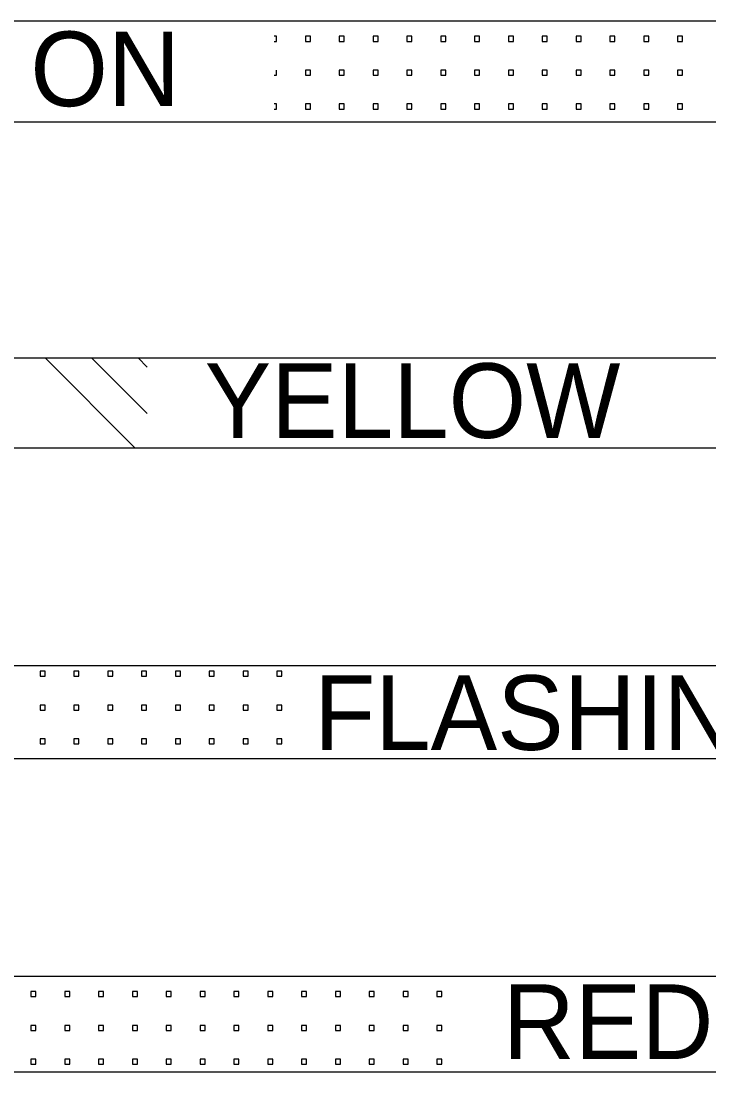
# Model space of a CAD drawing. Extents: x 15 to 764, y 7 to 487.
# Drawn here: x 610.69 to 642.97, y 134.67 to 183.98 of the extents above; entities that cross this region are included whole.
import ezdxf

# ---------------------------------------------------------------- set-up
doc = ezdxf.new("R2010")
doc.units = 0
doc.layers.add('Default', color=7, linetype='Continuous')
doc.layers.add('TextStructures', color=7, linetype='Continuous')

msp = doc.modelspace()

# ---------------------------------------------------------------- linework, layer by layer
at = {"layer": 'Default'}
for p, q in [((756.61, 183.984), (462.687, 183.984)), ((462.687, 179.246), (756.61, 179.246)), ((462.687, 168.178), (756.61, 168.178)), ((462.687, 163.965), (756.61, 163.965)), ((462.687, 153.744), (756.61, 153.744)), ((462.687, 149.383), (756.61, 149.383)), ((462.687, 139.163), (756.61, 139.163)), ((462.687, 134.675), (756.61, 134.675))]:
    msp.add_line(p, q, dxfattribs=at)
for points in [[(622.677, 183.27), (622.573, 183.269)], [(622.573, 183.03), (622.677, 183.03)], [(622.677, 183.03), (622.677, 183.27)], [(624.267, 183.03), (624.267, 183.27), (624.03, 183.269), (624.03, 183.03), (624.267, 183.03)], [(624.267, 183.03), (624.267, 183.27), (624.03, 183.269), (624.03, 183.03), (624.267, 183.03)], [(625.853, 183.03), (625.853, 183.27), (625.617, 183.269), (625.617, 183.03), (625.853, 183.03)], [(625.853, 183.03), (625.853, 183.27), (625.617, 183.269), (625.617, 183.03), (625.853, 183.03)], [(627.443, 183.03), (627.443, 183.27), (627.207, 183.269), (627.207, 183.03), (627.443, 183.03)], [(627.443, 183.03), (627.443, 183.27), (627.207, 183.269), (627.207, 183.03), (627.443, 183.03)], [(629.03, 183.03), (629.03, 183.27), (628.793, 183.269), (628.793, 183.03), (629.03, 183.03)], [(629.03, 183.03), (629.03, 183.27), (628.793, 183.269), (628.793, 183.03), (629.03, 183.03)], [(630.619, 183.03), (630.619, 183.27), (630.383, 183.269), (630.383, 183.03), (630.619, 183.03)], [(630.619, 183.03), (630.619, 183.27), (630.383, 183.269), (630.383, 183.03), (630.619, 183.03)], [(632.206, 183.03), (632.206, 183.27), (631.969, 183.269), (631.969, 183.03), (632.206, 183.03)], [(632.206, 183.03), (632.206, 183.27), (631.969, 183.269), (631.969, 183.03), (632.206, 183.03)], [(633.795, 183.03), (633.795, 183.27), (633.559, 183.269), (633.559, 183.03), (633.795, 183.03)], [(633.795, 183.03), (633.795, 183.27), (633.559, 183.269), (633.559, 183.03), (633.795, 183.03)], [(635.382, 183.03), (635.382, 183.27), (635.145, 183.269), (635.145, 183.03), (635.382, 183.03)], [(635.382, 183.03), (635.382, 183.27), (635.145, 183.269), (635.145, 183.03), (635.382, 183.03)], [(636.972, 183.03), (636.972, 183.27), (636.735, 183.269), (636.735, 183.03), (636.972, 183.03)], [(636.972, 183.03), (636.972, 183.27), (636.735, 183.269), (636.735, 183.03), (636.972, 183.03)], [(638.558, 183.03), (638.558, 183.27), (638.321, 183.269), (638.321, 183.03), (638.558, 183.03)], [(638.558, 183.03), (638.558, 183.27), (638.321, 183.269), (638.321, 183.03), (638.558, 183.03)], [(640.148, 183.03), (640.148, 183.27), (639.911, 183.269), (639.911, 183.03), (640.148, 183.03)], [(640.148, 183.03), (640.148, 183.27), (639.911, 183.269), (639.911, 183.03), (640.148, 183.03)], [(641.734, 183.03), (641.734, 183.27), (641.498, 183.269), (641.498, 183.03), (641.734, 183.03)], [(641.734, 183.03), (641.734, 183.27), (641.498, 183.269), (641.498, 183.03), (641.734, 183.03)], [(622.677, 181.443), (622.677, 181.683)], [(624.267, 181.443), (624.267, 181.683), (624.03, 181.682), (624.03, 181.443), (624.267, 181.443)], [(624.267, 181.443), (624.267, 181.683), (624.03, 181.682), (624.03, 181.443), (624.267, 181.443)], [(625.853, 181.443), (625.853, 181.683), (625.617, 181.682), (625.617, 181.443), (625.853, 181.443)], [(625.853, 181.443), (625.853, 181.683), (625.617, 181.682), (625.617, 181.443), (625.853, 181.443)], [(627.443, 181.443), (627.443, 181.683), (627.207, 181.682), (627.207, 181.443), (627.443, 181.443)], [(627.443, 181.443), (627.443, 181.683), (627.207, 181.682), (627.207, 181.443), (627.443, 181.443)], [(629.03, 181.443), (629.03, 181.683), (628.793, 181.682), (628.793, 181.443), (629.03, 181.443)], [(629.03, 181.443), (629.03, 181.683), (628.793, 181.682), (628.793, 181.443), (629.03, 181.443)], [(630.619, 181.443), (630.619, 181.683), (630.383, 181.682), (630.383, 181.443), (630.619, 181.443)], [(630.619, 181.443), (630.619, 181.683), (630.383, 181.682), (630.383, 181.443), (630.619, 181.443)], [(632.206, 181.443), (632.206, 181.683), (631.969, 181.682), (631.969, 181.443), (632.206, 181.443)], [(632.206, 181.443), (632.206, 181.683), (631.969, 181.682), (631.969, 181.443), (632.206, 181.443)], [(633.795, 181.443), (633.795, 181.683), (633.559, 181.682), (633.559, 181.443), (633.795, 181.443)], [(633.795, 181.443), (633.795, 181.683), (633.559, 181.682), (633.559, 181.443), (633.795, 181.443)], [(635.382, 181.443), (635.382, 181.683), (635.145, 181.682), (635.145, 181.443), (635.382, 181.443)], [(635.382, 181.443), (635.382, 181.683), (635.145, 181.682), (635.145, 181.443), (635.382, 181.443)], [(636.972, 181.443), (636.972, 181.683), (636.735, 181.682), (636.735, 181.443), (636.972, 181.443)], [(636.972, 181.443), (636.972, 181.683), (636.735, 181.682), (636.735, 181.443), (636.972, 181.443)], [(638.558, 181.443), (638.558, 181.683), (638.321, 181.682), (638.321, 181.443), (638.558, 181.443)], [(638.558, 181.443), (638.558, 181.683), (638.321, 181.682), (638.321, 181.443), (638.558, 181.443)], [(640.148, 181.443), (640.148, 181.683), (639.911, 181.682), (639.911, 181.443), (640.148, 181.443)], [(640.148, 181.443), (640.148, 181.683), (639.911, 181.682), (639.911, 181.443), (640.148, 181.443)], [(641.734, 181.443), (641.734, 181.683), (641.498, 181.682), (641.498, 181.443), (641.734, 181.443)], [(641.734, 181.443), (641.734, 181.683), (641.498, 181.682), (641.498, 181.443), (641.734, 181.443)], [(622.573, 181.443), (622.677, 181.443)], [(622.677, 180.094), (622.573, 180.094)], [(622.677, 179.854), (622.677, 180.094)], [(624.267, 179.854), (624.267, 180.094), (624.03, 180.093), (624.03, 179.854), (624.267, 179.854)], [(624.267, 179.854), (624.267, 180.094), (624.03, 180.093), (624.03, 179.854), (624.267, 179.854)], [(625.853, 179.854), (625.853, 180.094), (625.617, 180.093), (625.617, 179.854), (625.853, 179.854)], [(625.853, 179.854), (625.853, 180.094), (625.617, 180.093), (625.617, 179.854), (625.853, 179.854)], [(627.443, 179.854), (627.443, 180.094), (627.207, 180.093), (627.207, 179.854), (627.443, 179.854)], [(627.443, 179.854), (627.443, 180.094), (627.207, 180.093), (627.207, 179.854), (627.443, 179.854)], [(629.03, 179.854), (629.03, 180.094), (628.793, 180.093), (628.793, 179.854), (629.03, 179.854)], [(629.03, 179.854), (629.03, 180.094), (628.793, 180.093), (628.793, 179.854), (629.03, 179.854)], [(630.619, 179.854), (630.619, 180.094), (630.383, 180.093), (630.383, 179.854), (630.619, 179.854)], [(630.619, 179.854), (630.619, 180.094), (630.383, 180.093), (630.383, 179.854), (630.619, 179.854)], [(632.206, 179.854), (632.206, 180.094), (631.969, 180.093), (631.969, 179.854), (632.206, 179.854)], [(632.206, 179.854), (632.206, 180.094), (631.969, 180.093), (631.969, 179.854), (632.206, 179.854)], [(633.795, 179.854), (633.795, 180.094), (633.559, 180.093), (633.559, 179.854), (633.795, 179.854)], [(633.795, 179.854), (633.795, 180.094), (633.559, 180.093), (633.559, 179.854), (633.795, 179.854)], [(635.382, 179.854), (635.382, 180.094), (635.145, 180.093), (635.145, 179.854), (635.382, 179.854)], [(635.382, 179.854), (635.382, 180.094), (635.145, 180.093), (635.145, 179.854), (635.382, 179.854)], [(636.972, 179.854), (636.972, 180.094), (636.735, 180.093), (636.735, 179.854), (636.972, 179.854)], [(636.972, 179.854), (636.972, 180.094), (636.735, 180.093), (636.735, 179.854), (636.972, 179.854)], [(638.558, 179.854), (638.558, 180.094), (638.321, 180.093), (638.321, 179.854), (638.558, 179.854)], [(638.558, 179.854), (638.558, 180.094), (638.321, 180.093), (638.321, 179.854), (638.558, 179.854)], [(640.148, 179.854), (640.148, 180.094), (639.911, 180.093), (639.911, 179.854), (640.148, 179.854)], [(640.148, 179.854), (640.148, 180.094), (639.911, 180.093), (639.911, 179.854), (640.148, 179.854)], [(641.734, 179.854), (641.734, 180.094), (641.498, 180.093), (641.498, 179.854), (641.734, 179.854)], [(641.734, 179.854), (641.734, 180.094), (641.498, 180.093), (641.498, 179.854), (641.734, 179.854)], [(622.573, 179.854), (622.677, 179.854)], [(611.821, 168.178), (616.034, 163.965)], [(614, 168.178), (616.609, 165.568)], [(616.178, 168.178), (616.609, 167.747)], [(611.816, 153.239), (611.816, 153.478), (611.579, 153.477), (611.579, 153.239), (611.816, 153.239)], [(611.816, 153.239), (611.816, 153.478), (611.579, 153.477), (611.579, 153.239), (611.816, 153.239)], [(613.402, 153.239), (613.402, 153.478), (613.166, 153.477), (613.166, 153.239), (613.402, 153.239)], [(613.402, 153.239), (613.402, 153.478), (613.166, 153.477), (613.166, 153.239), (613.402, 153.239)], [(614.992, 153.239), (614.992, 153.478), (614.756, 153.477), (614.756, 153.239), (614.992, 153.239)], [(614.992, 153.239), (614.992, 153.478), (614.756, 153.477), (614.756, 153.239), (614.992, 153.239)], [(616.579, 153.239), (616.579, 153.478), (616.342, 153.477), (616.342, 153.239), (616.579, 153.239)], [(616.579, 153.239), (616.579, 153.478), (616.342, 153.477), (616.342, 153.239), (616.579, 153.239)], [(618.168, 153.239), (618.168, 153.478), (617.932, 153.477), (617.932, 153.239), (618.168, 153.239)], [(618.168, 153.239), (618.168, 153.478), (617.932, 153.477), (617.932, 153.239), (618.168, 153.239)], [(619.755, 153.239), (619.755, 153.478), (619.518, 153.477), (619.518, 153.239), (619.755, 153.239)], [(619.755, 153.239), (619.755, 153.478), (619.518, 153.477), (619.518, 153.239), (619.755, 153.239)], [(621.344, 153.239), (621.344, 153.478), (621.108, 153.477), (621.108, 153.239), (621.344, 153.239)], [(621.344, 153.239), (621.344, 153.478), (621.108, 153.477), (621.108, 153.239), (621.344, 153.239)], [(622.931, 153.239), (622.931, 153.478), (622.694, 153.477), (622.694, 153.239), (622.931, 153.239)], [(622.931, 153.239), (622.931, 153.478), (622.694, 153.477), (622.694, 153.239), (622.931, 153.239)], [(611.816, 151.65), (611.816, 151.89), (611.579, 151.888), (611.579, 151.65), (611.816, 151.65)], [(611.816, 151.65), (611.816, 151.89), (611.579, 151.888), (611.579, 151.65), (611.816, 151.65)], [(613.402, 151.65), (613.402, 151.89), (613.166, 151.888), (613.166, 151.65), (613.402, 151.65)], [(613.402, 151.65), (613.402, 151.89), (613.166, 151.888), (613.166, 151.65), (613.402, 151.65)], [(614.992, 151.65), (614.992, 151.89), (614.756, 151.888), (614.756, 151.65), (614.992, 151.65)], [(614.992, 151.65), (614.992, 151.89), (614.756, 151.888), (614.756, 151.65), (614.992, 151.65)], [(616.579, 151.65), (616.579, 151.89), (616.342, 151.888), (616.342, 151.65), (616.579, 151.65)], [(616.579, 151.65), (616.579, 151.89), (616.342, 151.888), (616.342, 151.65), (616.579, 151.65)], [(618.168, 151.65), (618.168, 151.89), (617.932, 151.888), (617.932, 151.65), (618.168, 151.65)], [(618.168, 151.65), (618.168, 151.89), (617.932, 151.888), (617.932, 151.65), (618.168, 151.65)], [(619.755, 151.65), (619.755, 151.89), (619.518, 151.888), (619.518, 151.65), (619.755, 151.65)], [(619.755, 151.65), (619.755, 151.89), (619.518, 151.888), (619.518, 151.65), (619.755, 151.65)], [(621.344, 151.65), (621.344, 151.89), (621.108, 151.888), (621.108, 151.65), (621.344, 151.65)], [(621.344, 151.65), (621.344, 151.89), (621.108, 151.888), (621.108, 151.65), (621.344, 151.65)], [(622.931, 151.65), (622.931, 151.89), (622.694, 151.888), (622.694, 151.65), (622.931, 151.65)], [(622.931, 151.65), (622.931, 151.89), (622.694, 151.888), (622.694, 151.65), (622.931, 151.65)], [(611.816, 150.063), (611.816, 150.302), (611.579, 150.301), (611.579, 150.063), (611.816, 150.063)], [(611.816, 150.063), (611.816, 150.302), (611.579, 150.301), (611.579, 150.063), (611.816, 150.063)], [(613.402, 150.063), (613.402, 150.302), (613.166, 150.301), (613.166, 150.063), (613.402, 150.063)], [(613.402, 150.063), (613.402, 150.302), (613.166, 150.301), (613.166, 150.063), (613.402, 150.063)], [(614.992, 150.063), (614.992, 150.302), (614.756, 150.301), (614.756, 150.063), (614.992, 150.063)], [(614.992, 150.063), (614.992, 150.302), (614.756, 150.301), (614.756, 150.063), (614.992, 150.063)], [(616.579, 150.063), (616.579, 150.302), (616.342, 150.301), (616.342, 150.063), (616.579, 150.063)], [(616.579, 150.063), (616.579, 150.302), (616.342, 150.301), (616.342, 150.063), (616.579, 150.063)], [(618.168, 150.063), (618.168, 150.302), (617.932, 150.301), (617.932, 150.063), (618.168, 150.063)], [(618.168, 150.063), (618.168, 150.302), (617.932, 150.301), (617.932, 150.063), (618.168, 150.063)], [(619.755, 150.063), (619.755, 150.302), (619.518, 150.301), (619.518, 150.063), (619.755, 150.063)], [(619.755, 150.063), (619.755, 150.302), (619.518, 150.301), (619.518, 150.063), (619.755, 150.063)], [(621.344, 150.063), (621.344, 150.302), (621.108, 150.301), (621.108, 150.063), (621.344, 150.063)], [(621.344, 150.063), (621.344, 150.302), (621.108, 150.301), (621.108, 150.063), (621.344, 150.063)], [(622.931, 150.063), (622.931, 150.302), (622.694, 150.301), (622.694, 150.063), (622.931, 150.063)], [(622.931, 150.063), (622.931, 150.302), (622.694, 150.301), (622.694, 150.063), (622.931, 150.063)], [(611.385, 138.212), (611.385, 138.452), (611.148, 138.451), (611.148, 138.212), (611.385, 138.212)], [(611.385, 138.212), (611.385, 138.452), (611.148, 138.451), (611.148, 138.212), (611.385, 138.212)], [(612.974, 138.212), (612.974, 138.452), (612.738, 138.451), (612.738, 138.212), (612.974, 138.212)], [(612.974, 138.212), (612.974, 138.452), (612.738, 138.451), (612.738, 138.212), (612.974, 138.212)], [(614.561, 138.212), (614.561, 138.452), (614.324, 138.451), (614.324, 138.212), (614.561, 138.212)], [(614.561, 138.212), (614.561, 138.452), (614.324, 138.451), (614.324, 138.212), (614.561, 138.212)], [(616.151, 138.212), (616.151, 138.452), (615.914, 138.451), (615.914, 138.212), (616.151, 138.212)], [(616.151, 138.212), (616.151, 138.452), (615.914, 138.451), (615.914, 138.212), (616.151, 138.212)], [(617.737, 138.212), (617.737, 138.452), (617.5, 138.451), (617.5, 138.212), (617.737, 138.212)], [(617.737, 138.212), (617.737, 138.452), (617.5, 138.451), (617.5, 138.212), (617.737, 138.212)], [(619.327, 138.212), (619.327, 138.452), (619.09, 138.451), (619.09, 138.212), (619.327, 138.212)], [(619.327, 138.212), (619.327, 138.452), (619.09, 138.451), (619.09, 138.212), (619.327, 138.212)], [(620.913, 138.212), (620.913, 138.452), (620.676, 138.451), (620.676, 138.212), (620.913, 138.212)], [(620.913, 138.212), (620.913, 138.452), (620.676, 138.451), (620.676, 138.212), (620.913, 138.212)], [(622.503, 138.212), (622.503, 138.452), (622.266, 138.451), (622.266, 138.212), (622.503, 138.212)], [(622.503, 138.212), (622.503, 138.452), (622.266, 138.451), (622.266, 138.212), (622.503, 138.212)], [(624.089, 138.212), (624.089, 138.452), (623.853, 138.451), (623.853, 138.212), (624.089, 138.212)], [(624.089, 138.212), (624.089, 138.452), (623.853, 138.451), (623.853, 138.212), (624.089, 138.212)], [(625.679, 138.212), (625.679, 138.452), (625.442, 138.451), (625.442, 138.212), (625.679, 138.212)], [(625.679, 138.212), (625.679, 138.452), (625.442, 138.451), (625.442, 138.212), (625.679, 138.212)], [(627.265, 138.212), (627.265, 138.452), (627.029, 138.451), (627.029, 138.212), (627.265, 138.212)], [(627.265, 138.212), (627.265, 138.452), (627.029, 138.451), (627.029, 138.212), (627.265, 138.212)], [(628.855, 138.212), (628.855, 138.452), (628.619, 138.451), (628.619, 138.212), (628.855, 138.212)], [(628.855, 138.212), (628.855, 138.452), (628.619, 138.451), (628.619, 138.212), (628.855, 138.212)], [(630.442, 138.212), (630.442, 138.452), (630.205, 138.451), (630.205, 138.212), (630.442, 138.212)], [(630.442, 138.212), (630.442, 138.452), (630.205, 138.451), (630.205, 138.212), (630.442, 138.212)], [(611.385, 136.624), (611.385, 136.863), (611.148, 136.862), (611.148, 136.624), (611.385, 136.624)], [(611.385, 136.624), (611.385, 136.863), (611.148, 136.862), (611.148, 136.624), (611.385, 136.624)], [(612.974, 136.624), (612.974, 136.863), (612.738, 136.862), (612.738, 136.624), (612.974, 136.624)], [(612.974, 136.624), (612.974, 136.863), (612.738, 136.862), (612.738, 136.624), (612.974, 136.624)], [(614.561, 136.624), (614.561, 136.863), (614.324, 136.862), (614.324, 136.624), (614.561, 136.624)], [(614.561, 136.624), (614.561, 136.863), (614.324, 136.862), (614.324, 136.624), (614.561, 136.624)], [(616.151, 136.624), (616.151, 136.863), (615.914, 136.862), (615.914, 136.624), (616.151, 136.624)], [(616.151, 136.624), (616.151, 136.863), (615.914, 136.862), (615.914, 136.624), (616.151, 136.624)], [(617.737, 136.624), (617.737, 136.863), (617.5, 136.862), (617.5, 136.624), (617.737, 136.624)], [(617.737, 136.624), (617.737, 136.863), (617.5, 136.862), (617.5, 136.624), (617.737, 136.624)], [(619.327, 136.624), (619.327, 136.863), (619.09, 136.862), (619.09, 136.624), (619.327, 136.624)], [(619.327, 136.624), (619.327, 136.863), (619.09, 136.862), (619.09, 136.624), (619.327, 136.624)], [(620.913, 136.624), (620.913, 136.863), (620.676, 136.862), (620.676, 136.624), (620.913, 136.624)], [(620.913, 136.624), (620.913, 136.863), (620.676, 136.862), (620.676, 136.624), (620.913, 136.624)], [(622.503, 136.624), (622.503, 136.863), (622.266, 136.862), (622.266, 136.624), (622.503, 136.624)], [(622.503, 136.624), (622.503, 136.863), (622.266, 136.862), (622.266, 136.624), (622.503, 136.624)], [(624.089, 136.624), (624.089, 136.863), (623.853, 136.862), (623.853, 136.624), (624.089, 136.624)], [(624.089, 136.624), (624.089, 136.863), (623.853, 136.862), (623.853, 136.624), (624.089, 136.624)], [(625.679, 136.624), (625.679, 136.863), (625.442, 136.862), (625.442, 136.624), (625.679, 136.624)], [(625.679, 136.624), (625.679, 136.863), (625.442, 136.862), (625.442, 136.624), (625.679, 136.624)], [(627.265, 136.624), (627.265, 136.863), (627.029, 136.862), (627.029, 136.624), (627.265, 136.624)], [(627.265, 136.624), (627.265, 136.863), (627.029, 136.862), (627.029, 136.624), (627.265, 136.624)], [(628.855, 136.624), (628.855, 136.863), (628.619, 136.862), (628.619, 136.624), (628.855, 136.624)], [(628.855, 136.624), (628.855, 136.863), (628.619, 136.862), (628.619, 136.624), (628.855, 136.624)], [(630.442, 136.624), (630.442, 136.863), (630.205, 136.862), (630.205, 136.624), (630.442, 136.624)], [(630.442, 136.624), (630.442, 136.863), (630.205, 136.862), (630.205, 136.624), (630.442, 136.624)], [(611.385, 135.036), (611.385, 135.276), (611.148, 135.275), (611.148, 135.036), (611.385, 135.036)], [(611.385, 135.036), (611.385, 135.276), (611.148, 135.275), (611.148, 135.036), (611.385, 135.036)], [(612.974, 135.036), (612.974, 135.276), (612.738, 135.275), (612.738, 135.036), (612.974, 135.036)], [(612.974, 135.036), (612.974, 135.276), (612.738, 135.275), (612.738, 135.036), (612.974, 135.036)], [(614.561, 135.036), (614.561, 135.276), (614.324, 135.275), (614.324, 135.036), (614.561, 135.036)], [(614.561, 135.036), (614.561, 135.276), (614.324, 135.275), (614.324, 135.036), (614.561, 135.036)], [(616.151, 135.036), (616.151, 135.276), (615.914, 135.275), (615.914, 135.036), (616.151, 135.036)], [(616.151, 135.036), (616.151, 135.276), (615.914, 135.275), (615.914, 135.036), (616.151, 135.036)], [(617.737, 135.036), (617.737, 135.276), (617.5, 135.275), (617.5, 135.036), (617.737, 135.036)], [(617.737, 135.036), (617.737, 135.276), (617.5, 135.275), (617.5, 135.036), (617.737, 135.036)], [(619.327, 135.036), (619.327, 135.276), (619.09, 135.275), (619.09, 135.036), (619.327, 135.036)], [(619.327, 135.036), (619.327, 135.276), (619.09, 135.275), (619.09, 135.036), (619.327, 135.036)], [(620.913, 135.036), (620.913, 135.276), (620.676, 135.275), (620.676, 135.036), (620.913, 135.036)], [(620.913, 135.036), (620.913, 135.276), (620.676, 135.275), (620.676, 135.036), (620.913, 135.036)], [(622.503, 135.036), (622.503, 135.276), (622.266, 135.275), (622.266, 135.036), (622.503, 135.036)], [(622.503, 135.036), (622.503, 135.276), (622.266, 135.275), (622.266, 135.036), (622.503, 135.036)], [(624.089, 135.036), (624.089, 135.276), (623.853, 135.275), (623.853, 135.036), (624.089, 135.036)], [(624.089, 135.036), (624.089, 135.276), (623.853, 135.275), (623.853, 135.036), (624.089, 135.036)], [(625.679, 135.036), (625.679, 135.276), (625.442, 135.275), (625.442, 135.036), (625.679, 135.036)], [(625.679, 135.036), (625.679, 135.276), (625.442, 135.275), (625.442, 135.036), (625.679, 135.036)], [(627.265, 135.036), (627.265, 135.276), (627.029, 135.275), (627.029, 135.036), (627.265, 135.036)], [(627.265, 135.036), (627.265, 135.276), (627.029, 135.275), (627.029, 135.036), (627.265, 135.036)], [(628.855, 135.036), (628.855, 135.276), (628.619, 135.275), (628.619, 135.036), (628.855, 135.036)], [(628.855, 135.036), (628.855, 135.276), (628.619, 135.275), (628.619, 135.036), (628.855, 135.036)], [(630.442, 135.036), (630.442, 135.276), (630.205, 135.275), (630.205, 135.036), (630.442, 135.036)], [(630.442, 135.036), (630.442, 135.276), (630.205, 135.275), (630.205, 135.036), (630.442, 135.036)]]:
    msp.add_lwpolyline(points, dxfattribs=at)

# ---------------------------------------------------------------- texts
at = {"layer": 'TextStructures'}
for s, p in [('ON', (611.127, 179.989)), ('YELLOW', (619.305, 164.424)), ('FLASHING RED', (624.448, 149.784)), ('RED', (633.296, 135.284))]:
    msp.add_text(s, height=3.5, rotation=0.0007, dxfattribs=at).set_placement(p)

doc.saveas('drawing.dxf')
